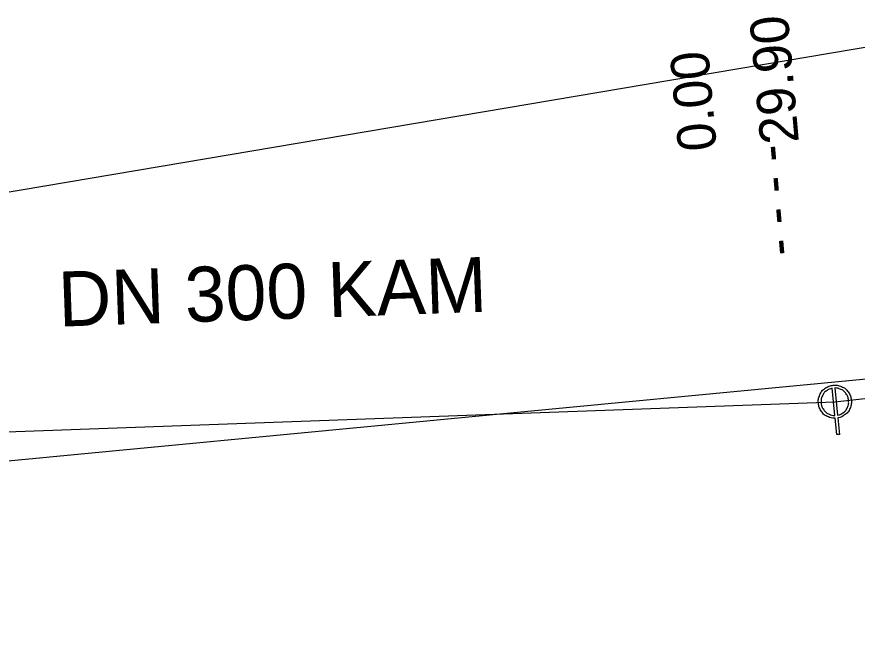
# Model space of a CAD drawing. Extents: x -818321 to -817653, y -1049725 to -1049329.
# Drawn here: x -817757.35 to -817742.06, y -1049388.03 to -1049376.58 of the extents above; entities that cross this region are included whole.
import ezdxf

# ---------------------------------------------------------------- set-up
doc = ezdxf.new("R2010")
doc.units = 0
doc.layers.add('Default', color=7, linetype='Continuous')
doc.layers.add('Level 0', color=7, linetype='Continuous')

msp = doc.modelspace()

# ---------------------------------------------------------------- linework, layer by layer
at = {"layer": 'Default'}
for points in [[(-817742.465, -1049383.833), (-817742.517, -1049383.339)], [(-817742.468, -1049383.334), (-817742.416, -1049383.828)], [(-817742.411, -1049383.879), (-817742.379, -1049384.178), (-817742.428, -1049384.183), (-817742.46, -1049383.884)]]:
    msp.add_lwpolyline(points, dxfattribs=at)
for points in [[(-817742.46, -1049383.884), (-817742.522, -1049383.887), (-817742.588, -1049383.858), (-817742.663, -1049383.827), (-817742.71, -1049383.76), (-817742.757, -1049383.693), (-817742.765, -1049383.615), (-817742.773, -1049383.537), (-817742.74, -1049383.461), (-817742.708, -1049383.385), (-817742.641, -1049383.339), (-817742.574, -1049383.293), (-817742.498, -1049383.285), (-817742.423, -1049383.278), (-817742.347, -1049383.309), (-817742.272, -1049383.339), (-817742.224, -1049383.407), (-817742.176, -1049383.474), (-817742.168, -1049383.552), (-817742.16, -1049383.63), (-817742.192, -1049383.705), (-817742.224, -1049383.78), (-817742.291, -1049383.827), (-817742.349, -1049383.868), (-817742.411, -1049383.879)], [(-817742.517, -1049383.339), (-817742.564, -1049383.348), (-817742.612, -1049383.381), (-817742.668, -1049383.419), (-817742.695, -1049383.482), (-817742.722, -1049383.545), (-817742.715, -1049383.61), (-817742.709, -1049383.675), (-817742.67, -1049383.73), (-817742.631, -1049383.785), (-817742.568, -1049383.812), (-817742.514, -1049383.835), (-817742.465, -1049383.833)], [(-817742.416, -1049383.828), (-817742.368, -1049383.82), (-817742.319, -1049383.786), (-817742.264, -1049383.747), (-817742.237, -1049383.685), (-817742.211, -1049383.622), (-817742.218, -1049383.558), (-817742.225, -1049383.493), (-817742.264, -1049383.437), (-817742.304, -1049383.381), (-817742.367, -1049383.355), (-817742.42, -1049383.333), (-817742.468, -1049383.334)]]:
    msp.add_open_spline(points, degree=3, dxfattribs=at)
at = {"layer": 'Level 0'}
for p, q in [((-817739.929, -1049376.803), (-817767.788, -1049381.512)), ((-817792.8, -1049388.031), (-817740.932, -1049383.074)), ((-817739.683, -1049383.281), (-817742.466, -1049383.589)), ((-817742.466, -1049383.589), (-817771.012, -1049384.628))]:
    msp.add_line(p, q, dxfattribs=at)

# ---------------------------------------------------------------- texts
for s, height, rotation, p in [('29.90', 0.7, 95, (-817743.12, -1049378.864)), ('0.00', 0.7, 95, (-817744.614, -1049378.995)), ('- - - -', 0.7, 275, (-817743.867, -1049378.929)), ('DN 300 KAM', 1, 2, (-817756.584, -1049382.219))]:
    msp.add_text(s, height=height, rotation=rotation, dxfattribs=at).set_placement(p)

doc.saveas('drawing.dxf')
